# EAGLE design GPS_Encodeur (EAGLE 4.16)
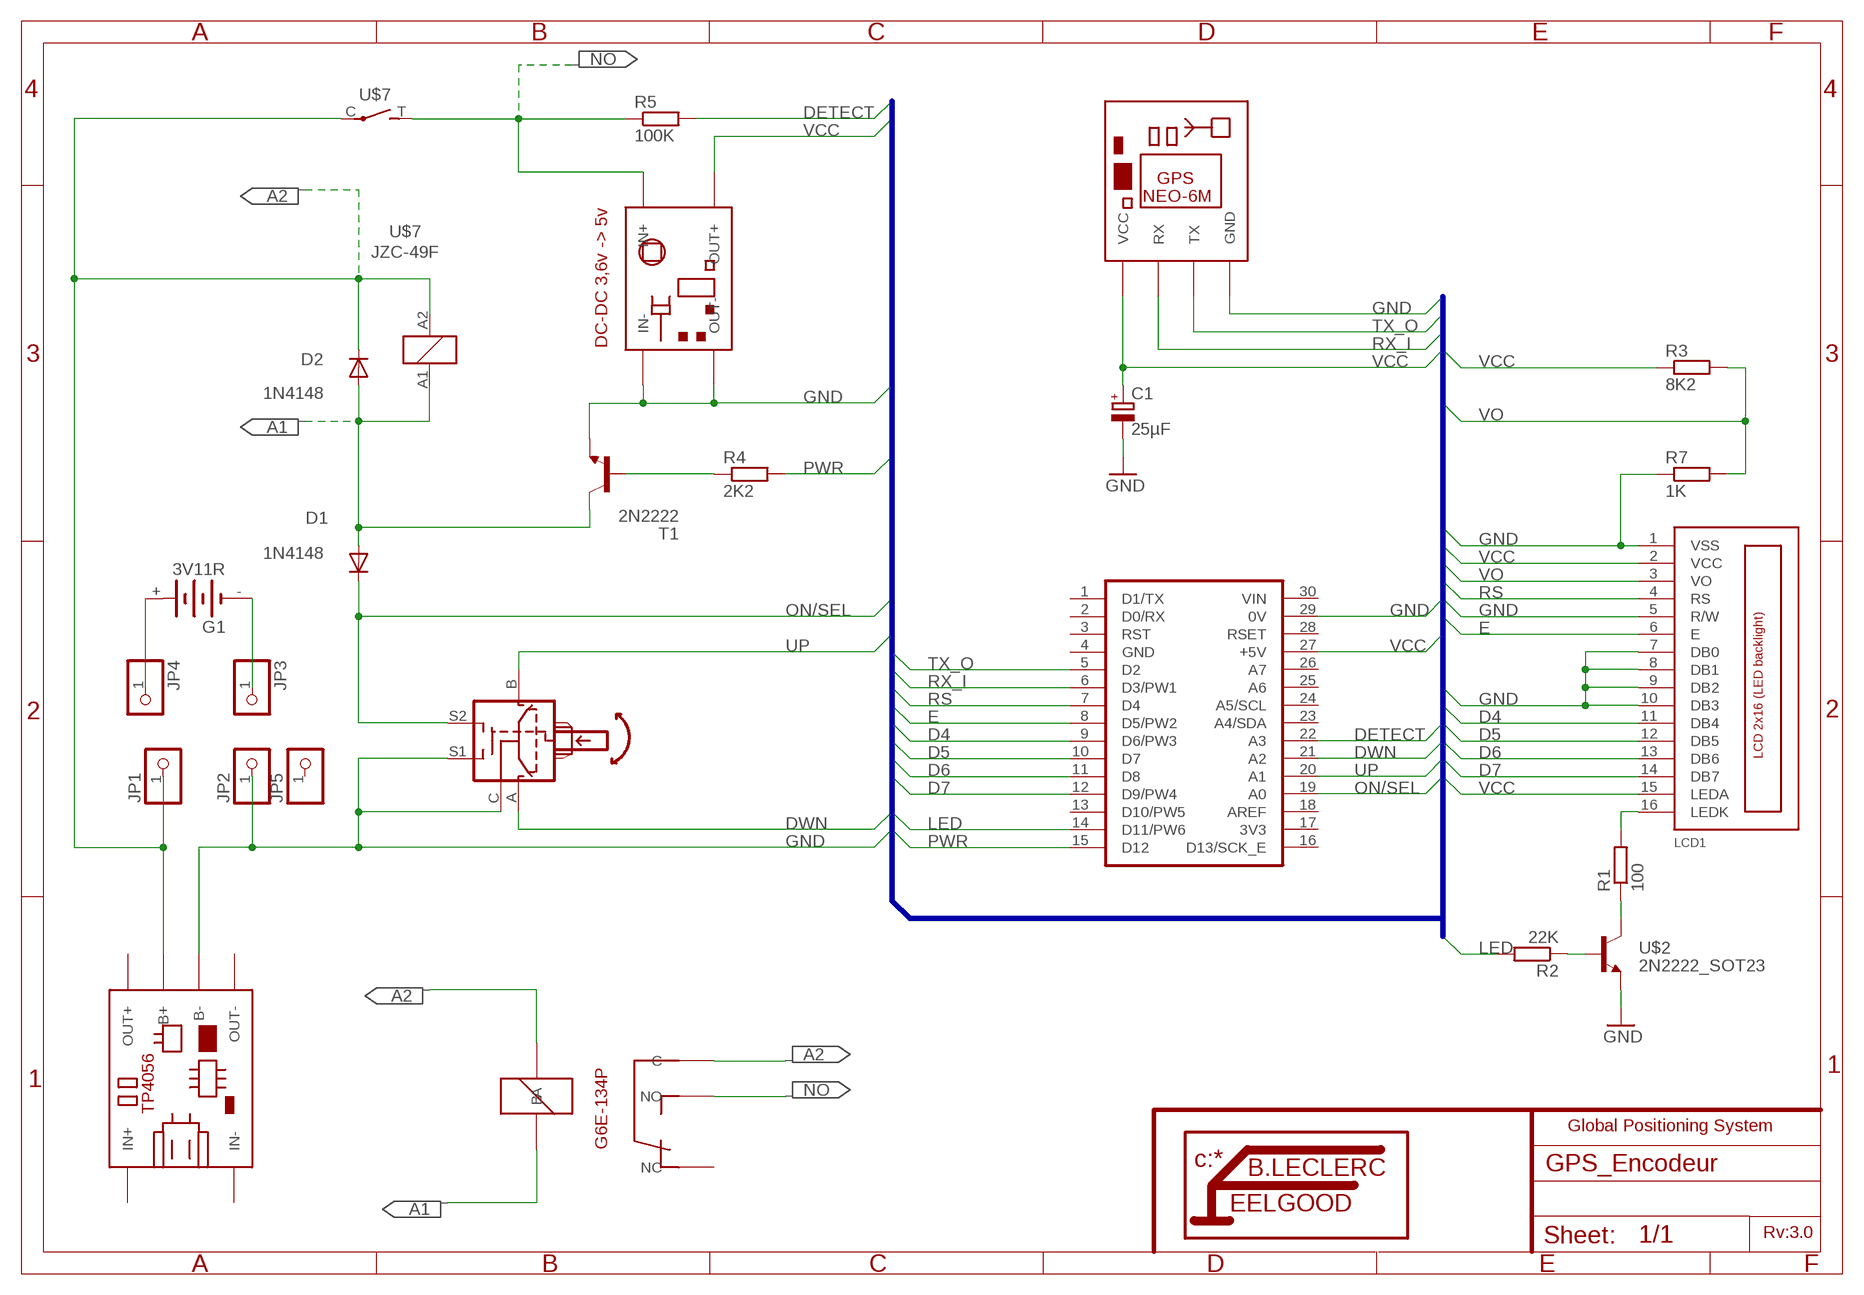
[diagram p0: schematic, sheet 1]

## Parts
C1  25µF  CPOL-EUE2.5-5  [E2,5-5]
D1  1N4148  DIODE-MINIMELF  [MINIMELF]
D2  1N4148  DIODE-MINIMELF  [MINIMELF]
G1  3V11R  [3V11R]
JP1  PINHD-1X1  [1X01]
JP2  PINHD-1X1  [1X01]
JP3  PINHD-1X1  [1X01]
JP4  PINHD-1X1  [1X01]
JP5  PINHD-1X1  [1X01]
LCD1  LCD_2X16_SIL  [HY-1602F]
R1  100  R-EU_0207/10  [0207/10]
R2  22K  R-EU_0207/10  [0207/10]
R3  8K2  R-EU_M1206  [M1206]
R4  2K2  R-EU_0207/12  [0207/12]
R5  100K  R-EU_0207/12  [0207/12]
R7  1K  R-EU_M1206  [M1206]
REL1  G6E-134P  [G6E-134P]
SW1  IMPULS_SWITCH  [IMPULS_SWITCH]
T1  2N2222  [TO18]
U1  NANO  [NANO]
U$2  2N2222_SOT23  [SOT23-BEC]
U$3  CHARGEUR_ION-LI  [CHARGEUR_ION-LI]
U$4  DC-DC_BOOST  [DC-DC_BOOST]
U$5  GY-NEO6MV2  [GY-NEO6MV2]
U$7  JZC-49F  [JZC-49F]

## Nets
A1: D1.A D2.A REL1.A T1.3(C) U$7.A1
A2: D2.C JP1.1 REL1.B REL1.C U$3.B+ U$7.A2 U$7.C(P)
D4: LCD1.11(DB4) U1.9(D6/PW3)
D5: LCD1.12(DB5) U1.10(D7)
D6: LCD1.13(DB6) U1.11(D8)
D7: LCD1.14(DB7) U1.12(D9/PW4)
DETECT: R5.2 U1.22(A3)
DWN: SW1.A U1.21(A2)
E: LCD1.6(E) U1.8(D5/PW2)
GND: C1.- JP2.1 LCD1.1(VSS) LCD1.5(R/W) LCD1.7(DB0) LCD1.8(DB1) LCD1.9(DB2) LCD1.10(DB3) R7.1 SW1.C SW1.S1 T1.1(E) U1.29(0V) U$2.E U$3.B- U$4.IN- U$4.OUT- U$5.GND
LED: R2.2 U1.14(D11/PW6)
N$3: R1.1 U$2.C
N$5: G1.+ JP4.1
N$6: LCD1.16(LEDK) R1.2
N$7: G1.- JP3.1
N$9: R2.1 U$2.B
N$10: R4.1 T1.2(B)
NO: R5.1 REL1.NO U$4.IN+ U$7.T(S)
ON/SEL: D1.C SW1.S2 U1.19(A0)
PWR: R4.2 U1.15(D12)
RS: LCD1.4(RS) U1.7(D4)
RX_I: U1.6(D3/PW1) U$5.RX
TX_O: U1.5(D2) U$5.TX
UP: SW1.B U1.20(A1)
VCC: C1.+ LCD1.2(VCC) LCD1.15(LEDA) R3.1 U1.27(+5V) U$4.OUT+ U$5.VCC
VO: LCD1.3(VO) R3.2 R7.2
Unconnected: JP5.1 REL1.NC U1.1(D1/TX) U1.2(D0/RX) U1.3(RST) U1.13(D10/PW5) U1.16(D13/SCK_E) U1.18(AREF) U1.23(A4/SDA) U1.24(A5/SCL) U1.25(A6) U1.26(A7) U1.28(RSET)

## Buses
B$1

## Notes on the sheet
- Global Positioning System
- Rv:3.0

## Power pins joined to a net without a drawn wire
3V3: U1.17(3V3)
GND: U1.4(GND)
IN+: U$3.IN+
IN-: U$3.IN-
OUT+: U$3.OUT+
OUT-: U$3.OUT-
VIN: U1.30(VIN)

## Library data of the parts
C1 = rcl:CPOL-EU: POLARIZED CAPACITOR, European symbol
D1 D2 = diode:DIODE-: DIODE
G1 = battery:3V11R: NC ACCU Varta
JP1-JP5 = pinhead:PINHD-1X1: PIN HEADER
LCD1 = lcd_2x16_led_backlight:LCD_2X16_SIL
R1-R5 R7 = rcl:R-EU_: RESISTOR, European symbol
REL1 = relay:G6E-134P
SW1 = switch:IMPULS_SWITCH
T1 = transistor:2N2222: NPN TRANSISTOR
U1 = Arduino:NANO
U$2 = transistor:2N2222_SOT23
U$3 = Arduino:CHARGEUR_ION-LI
U$4 = Arduino:DC-DC_BOOST
U$5 = Arduino:GY-NEO6MV2
U$7 = relay:JZC-49F

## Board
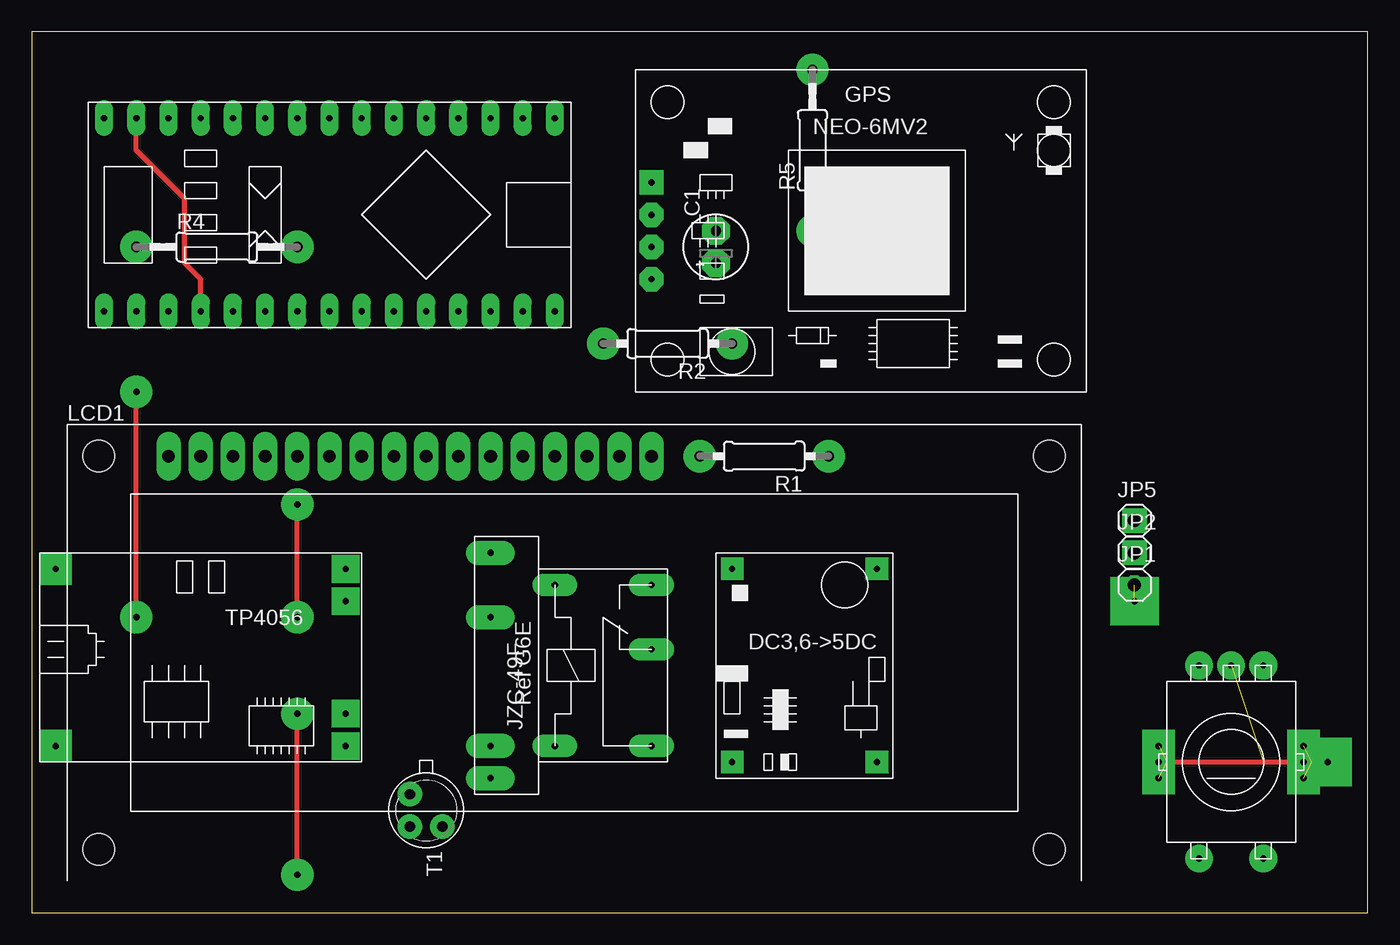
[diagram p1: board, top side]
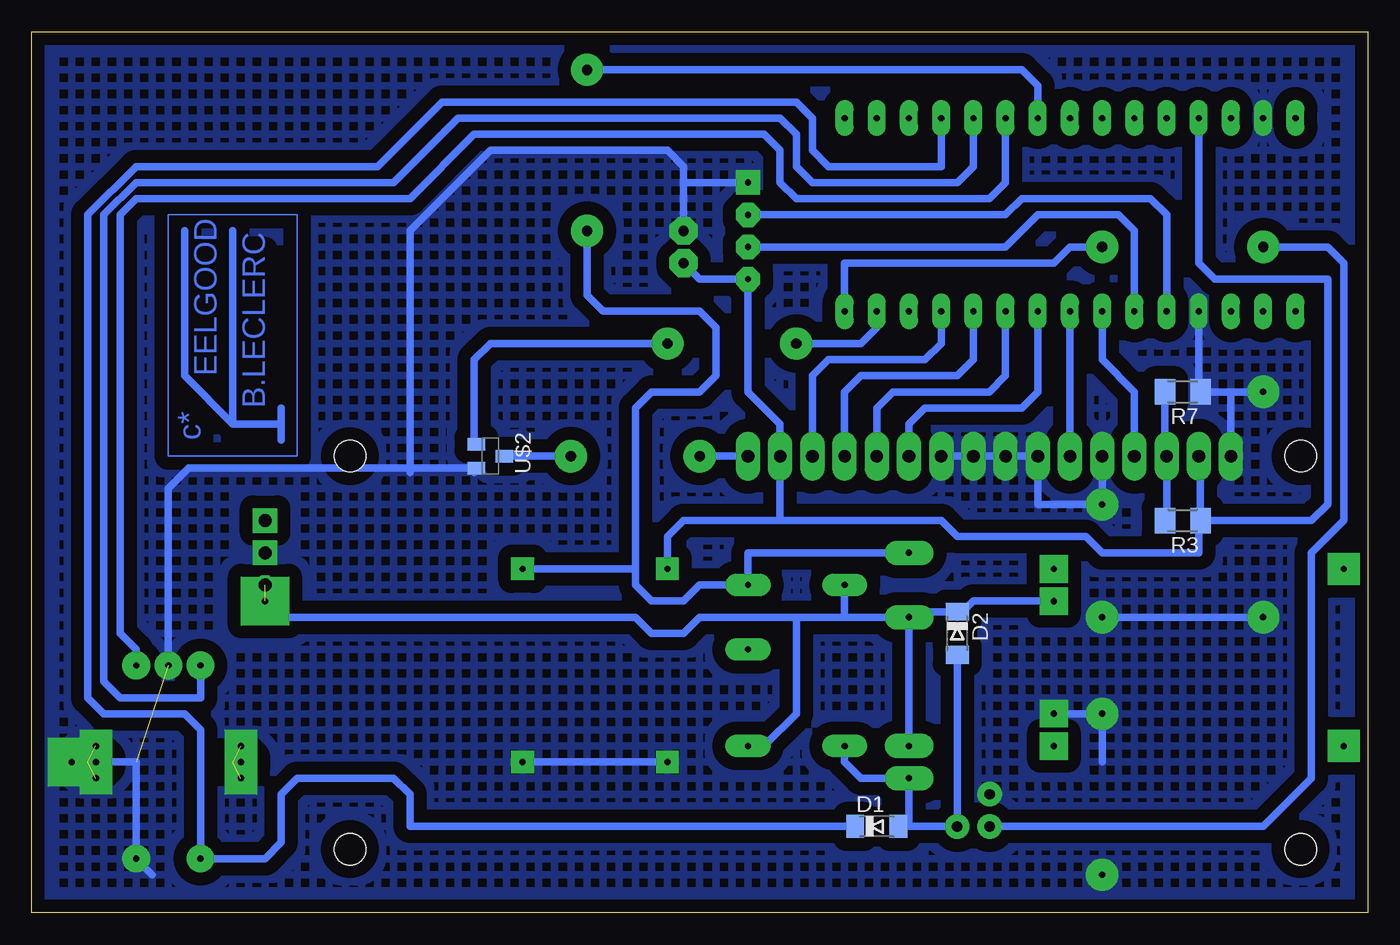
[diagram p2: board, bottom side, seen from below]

Size 105.39 x 69.52 mm. Coordinates in mm from the lower left corner, seen from the top.
Outline: 0,0 105.39,0 105.39,69.52 0,69.52 0,0
Copper layers (1*16): Top 0.035mm / dielectric 1.5mm / Bottom 0.035mm
Design rules "default": minimum track width 10mil, minimum drill 24mil, track to track 8mil, track to pad 8mil, pad to pad 8mil, via to via 8mil, smd to smd 8mil, copper to edge 40mil, drill to drill 8mil, minimum pad ring 10mil, minimum via ring 8mil, stop-mask expansion 4mil, vias tented up to drill 0mil, thermal gap 10mil

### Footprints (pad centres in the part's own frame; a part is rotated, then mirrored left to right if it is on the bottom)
E2,5-5 = drill 0.813 pad 1.6 round: + -1.27,0 | drill 0.813 pad 1.6 octagon: - 1.27,0
MINIMELF = smd 1.4 x 1.8: A 1.7,0; C -1.7,0
3V11R = drill 1.118 pad 2.54 octagon: + -5.08,0; - 5.08,0
1X01 = drill 1.016 octagon: 1 0,0
HY-1602F = drill 1 pad 1.93 long: 1 2.54,0; 2 5.08,0; 3 7.62,0; 4 10.16,0; 5 12.7,0; 6 15.24,0; 7 17.78,0; 8 20.32,0; 9 22.86,0; 10 25.4,0; 11 27.94,0; 12 30.48,0; 13 33.02,0; 14 35.56,0; 15 38.1,0; 16 40.64,0 | hole 2.5: -2.96,0; 72.04,0; -2.96,-31; 72.04,-31
0207/10 = drill 0.813 octagon: 1 -5.08,0; 2 5.08,0
M1206 = smd 1.6 x 2: 1 -1.4,0; 2 1.4,0
0207/12 = drill 0.813 octagon: 1 -6.35,0; 2 6.35,0
G6E-134P = drill 0.5 pad 1.778 long: A 0,3.81; B 12.7,3.81; C 0,-3.81; NC 7.62,-3.81; NO 12.7,-3.81
IMPULS_SWITCH = drill 0.5 pad 1.676 octagon: A -7.62,2.54; B -7.62,-2.54; C -7.62,0; S1 7.62,2.54; S2 7.62,-2.54 | drill 0.5 pad 2.54 octagon: P$1 0,5.715; P$2 0,-5.715
TO18 = drill 0.813 octagon: 1 -1.27,-1.27; 2 1.27,-1.27; 3 1.27,1.27
NANO = drill 0.5 pad 1.422 long: 1 -7.62,17.78; 2 -7.62,15.24; 3 -7.62,12.7; 4 -7.62,10.16; 5 -7.62,7.62; 6 -7.62,5.08; 7 -7.62,2.54; 8 -7.62,0; 9 -7.62,-2.54; 10 -7.62,-5.08; 11 -7.62,-7.62; 12 -7.62,-10.16; 13 -7.62,-12.7; 14 -7.62,-15.24; 15 -7.62,-17.78; 16 7.62,-17.78; 17 7.62,-15.24; 18 7.62,-12.7; 19 7.62,-10.16; 20 7.62,-7.62; 21 7.62,-5.08; 22 7.62,-2.54; 23 7.62,0; 24 7.62,2.54; 25 7.62,5.08; 26 7.62,7.62; 27 7.62,10.16; 28 7.62,12.7; 29 7.62,15.24; 30 7.62,17.78
SOT23-BEC = smd 1 x 1.4: B -0.95,-1.1; C 0,1.1; E 0.95,-1.1
CHARGEUR_ION-LI = drill 0.5 pad 2.184 square: B+ 24.13,12.7; B- 24.13,3.81; OUT+ 24.13,15.24; OUT- 24.13,1.27 | drill 0.5 pad 2.54 square: IN+ 1.27,15.24; IN- 1.27,1.27
DC-DC_BOOST = drill 0.5 pad 1.778 square: IN+ 0,0; IN- 0,15.24; OUT+ 11.43,0; OUT- 11.43,15.24
GY-NEO6MV2 = drill 0.5 pad 1.93 square: GND 1.27,3.81 | drill 0.5 pad 1.93 octagon: RX 1.27,-1.27; TX 1.27,1.27; VCC 1.27,-3.81
JZC-49F = drill 0.5 pad 1.93 long: A1 0,0; A2 2.54,0; C 12.7,0; T 17.78,0

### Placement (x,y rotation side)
C1  53.97,52.54 90 top
D1  38.73,6.82 0 bottom
D2  32.38,22.06 270 bottom
G1  not placed on the board
JP1  86.99,25.87 0 top
JP2  86.99,28.41 0 top
JP3  not placed on the board
JP4  not placed on the board
JP5  86.99,30.95 0 top
LCD1  8.25,36.03 0 top
R1  57.78,36.03 180 top
R2  50.16,44.92 180 top
R3  14.6,30.95 180 bottom
R4  14.6,52.54 0 top
R5  61.59,60.16 90 top
R7  14.6,41.11 180 bottom
REL1  45.08,13.17 90 top
SW1  94.61,11.9 270 top
T1  31.11,8.09 270 top
U1  23.49,55.08 90 top
U$2  69.21,36.03 270 bottom
U$3  0.63,11.9 0 top
U$4  66.67,27.14 180 top
U$5  47.62,53.81 0 top
U$6  [LITTFEEL]  81.91,38.57 90 bottom
U$7  36.19,10.63 90 top

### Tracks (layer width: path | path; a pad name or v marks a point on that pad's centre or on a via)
A1
  Bottom 0.61: 36.19,6.82 T1.3 D2.A | 36.19,6.82 D1.A | 36.19,6.82 U$7.A1 40,10.63 41.27,11.9 REL1.A
A2  (via drill 0.5 pad 1.93, 0.5 pad 3.81)  (1 unrouted)
  Bottom 0.61: U$3.B+ 31.11,24.6 32.38,23.33 D2.C 37.03,23.76 U$7.C | U$7.C U$7.A2 | U$7.C 41.27,23.33 | 41.27,23.33 45.08,23.33 | 45.08,23.33 52.7,23.33 53.97,22.06 56.51,22.06 57.78,23.33 85.72,23.33 v86.99,24.6 | 41.27,23.33 REL1.B | REL1.C 47.62,13.17 45.08,15.71 45.08,23.33
D4
  Bottom 0.61: U1.9 26.03,41.11 27.3,39.84 34.92,39.84 36.19,38.57 LCD1.11
D5
  Bottom 0.61: U1.10 28.57,42.38 29.84,41.11 37.46,41.11 38.73,39.84 LCD1.12
D6
  Bottom 0.61: U1.11 31.11,43.65 32.38,42.38 40,42.38 41.27,41.11 LCD1.13
D7
  Bottom 0.61: U1.12 33.65,44.92 34.92,43.65 42.54,43.65 43.81,42.38 LCD1.14
DETECT
  Bottom 0.61: U1.22 26.03,65.24 27.3,66.51 R5.2
DWN
  Bottom 0.61: U1.21 28.57,57.62 29.84,56.35 45.08,56.35 46.35,57.62 46.35,60.16 47.62,61.43 70.48,61.43 75.56,56.35 97.15,56.35 98.42,55.08 98.42,22.06 97.15,20.79 SW1.A
E
  Bottom 0.61: LCD1.6 U1.8
GND  (via drill 0.5 pad 1.27, 0.5 pad 1.93, 0.5 pad 2.18, 0.5 pad 2.54, 0.5 pad 3.81)  (6 unrouted)
  Top 0.406: 89.53,11.9 100.96,11.9 | U1.29 8.25,60.16 12.06,56.35 12.06,51.27 13.33,50 U1.4 | v20.95,23.33 v20.95,32.22 | v20.95,3.01 v20.95,15.71 | v8.25,23.33 v8.25,41.11 v8.25,23.33
  Bottom 0.61: U$4.OUT- U$4.IN- | 95.88,3.01 SW1.S1 97.15,11.9 100.96,11.9 | U$5.GND 53.97,57.62 C1.- 53.97,58.89 55.24,60.16 69.21,60.16 75.56,53.81 75.56,35.08 | LCD1.1 10.79,41.11 13.33,41.11 | 13.33,41.11 R7.1 | LCD1.10 LCD1.9 LCD1.8 LCD1.7 26.03,32.22 v20.95,32.22 LCD1.5 | 13.33,41.11 U1.4 | 70.48,34.76 70.31,34.93 U$2.E 75.56,35.08 | 75.56,35.08 93.02,35.08 94.61,33.49 SW1.C | 75.56,35.08 75.56,34.76 | v8.25,41.11 13.33,41.11 | v8.25,23.33 v20.95,23.33 | U$3.B- v20.95,15.71 20.95,11.9
  other vias: 53.97,53.81 10.79,36.03 20.95,36.03 26.03,36.03 28.57,36.03 31.11,36.03 33.65,36.03 94.61,19.52 97.15,4.28 88.89,13.17 88.89,10.63 100.32,13.17 100.32,10.63 29.84,9.36 86.99,28.41 102.23,11.9
  pour Bottom (isolate 1.016, no thermals, hatched): 0.63,69.05 104.77,69.05 104.77,0.47 0.63,0.47
LED
  Bottom 0.61: U1.14 38.73,46.19 40,44.92 R2.2
N$1  (via drill 0.5 pad 2.54)
  other vias: 8.25,52.54
N$2  (via drill 0.5 pad 1.93)
  other vias: 86.99,30.95
N$3
  Bottom 0.61: R1.1 U$2.C
N$5  (1 unrouted)
N$6
  Bottom 0.61: LCD1.16 R1.2
N$7  (1 unrouted)
N$9
  Bottom 0.61: R2.1 69.21,44.92 70.48,43.65 70.48,37.3 70.31,37.13 U$2.B
N$10
  Bottom 0.61: R4.1 3.17,52.54 1.9,51.27 1.9,30.95 4.44,28.41 4.44,10.63 8.25,6.82 T1.2
N$11  (via drill 0.5 pad 2.54)
  other vias: 20.95,52.54
N$13  (via drill 0.5 pad 2.54)
  other vias: 45.08,44.92
N$14  (via drill 0.5 pad 2.54)
  other vias: 62.86,36.03
N$15  (via drill 0.5 pad 2.18)
  other vias: 53.97,51.27
N$16  (via drill 0.5 pad 2.54)
  other vias: 52.7,36.03
N$17  (via drill 0.5 pad 2.54)
  other vias: 55.24,44.92
N$18  (via drill 0.5 pad 2.18)
  other vias: 92.07,19.52
N$19  (via drill 0.5 pad 1.27)
  other vias: 13.33,36.03
N$20  (via drill 0.5 pad 2.54)
  other vias: 61.59,66.51
N$21  (via drill 0.5 pad 1.27)
  other vias: 38.73,36.03
N$22  (via drill 0.5 pad 1.27)
  other vias: 41.27,36.03
N$23  (via drill 0.5 pad 1.27)
  other vias: 48.89,36.03
N$24  (via drill 0.5 pad 1.27)
  other vias: 46.35,36.03
N$25  (via drill 0.5 pad 1.27)
  other vias: 43.81,36.03
N$26  (via drill 0.5 pad 1.27)
  other vias: 36.19,36.03
N$27  (via drill 0.5 pad 1.27)
  other vias: 15.87,36.03
N$28  (via drill 0.5 pad 1.27)
  other vias: 18.41,36.03
N$29  (via drill 0.5 pad 1.27)
  other vias: 23.49,36.03
N$30  (via drill 0.5 pad 2.18)
  other vias: 97.15,19.52
N$31  (via drill 0.5 pad 2.54)
  other vias: 61.59,53.81
N$40  (via drill 0.5 pad 1.93)
  other vias: 32.38,6.82
N$41  (via drill 0.5 pad 1.93)
  other vias: 29.84,6.82
N$44  (via drill 0.5 pad 2.18)
  other vias: 92.07,4.28
NO
  Bottom 0.61: R5.1 61.59,48.73 60.32,47.46 52.7,47.46 51.43,46.19 51.43,42.38 52.7,41.11 56.51,41.11 57.78,39.84 57.78,27.14 | 57.78,27.14 U$4.IN+ | U$7.T 48.89,28.41 REL1.NO 52.7,25.87 53.97,24.6 56.51,24.6 57.78,25.87 57.78,27.14
ON/SEL
  Bottom 0.61: U1.19 33.65,58.89 42.54,58.89 43.81,60.16 43.81,62.7 45.08,63.97 73.02,63.97 78.1,58.89 97.15,58.89 100.96,55.08 100.96,16.98 99.69,15.71 93.34,15.71 92.07,14.44 SW1.S2 86.99,4.28 85.72,5.55 85.72,9.36 84.45,10.63 76.83,10.63 75.56,9.36 75.56,6.82 D1.C
PWR
  Bottom 0.61: U1.15 41.27,51.27 24.76,51.27 23.49,52.54 R4.2
RS
  Bottom 0.61: U1.7 20.95,43.65 18.41,41.11 LCD1.4
RX_I
  Bottom 0.61: U$5.RX 28.57,52.54 26.03,55.08 19.68,55.08 18.41,53.81 U1.6
TX_O
  Bottom 0.61: U$5.TX 28.57,55.08 27.3,56.35 17.14,56.35 15.87,55.08 U1.5
UP
  Bottom 0.61: U1.20 31.11,58.89 32.38,57.62 43.81,57.62 45.08,58.89 45.08,61.43 46.35,62.7 71.75,62.7 76.83,57.62 97.15,57.62 99.69,55.08 99.69,18.25 98.42,16.98 92.07,16.98 SW1.B
VCC
  Bottom 0.61: C1.+ 52.7,50 U$5.VCC 48.89,41.11 46.35,38.57 LCD1.15 46.35,30.95 | R3.1 13.2,35.9 LCD1.2 | R3.1 4.44,30.95 3.17,32.22 3.17,50 12.06,50 13.33,51.27 U1.27 | 46.35,30.95 33.65,30.95 32.38,29.68 22.22,29.68 20.95,28.41 13.33,28.41 13.33,30.95 R3.1 | 46.35,30.95 53.97,30.95 55.24,29.68 U$4.OUT+
VO
  Bottom 0.61: R7.2 16,36.16 LCD1.3 15.87,30.95 R3.2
